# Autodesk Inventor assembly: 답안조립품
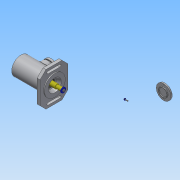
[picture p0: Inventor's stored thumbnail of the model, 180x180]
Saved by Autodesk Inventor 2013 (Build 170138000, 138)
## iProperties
Created: 2017-10
Part Number: 답안조립품
Document SubType Name: Assembly
Designer: Administrator
Author: Administrator
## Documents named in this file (20)
- C:\Users\Administrator\Desktop\471008V1005\답안조립품.iam
- C:\Users\Administrator\Desktop\471008V1005\본체.ipt
- C:\Users\Administrator\Desktop\471008V1005\V-벨트풀리.ipt
- C:\Users\Administrator\Desktop\471008V1005\너트 M10.ipt
- C:\Users\Administrator\Desktop\471008V1005\멈춤링 15 x 1.ipt
- C:\Users\Administrator\Desktop\471008V1005\멈춤링 35x1.6.ipt
- C:\Users\Administrator\Desktop\471008V1005\베어링 15 x 35 x 11.ipt
- C:\Users\Administrator\Desktop\471008V1005\볼트 M4 x 10.ipt
- C:\Users\Administrator\Desktop\471008V1005\부시1.ipt
- C:\Users\Administrator\Desktop\471008V1005\부시2.ipt
- C:\Users\Administrator\Desktop\471008V1005\사이드 커버.ipt
- 사이드 커버.ipt
- C:\Users\Administrator\Desktop\471008V1005\십자볼트 M3 x 10.ipt
- C:\Users\Administrator\Desktop\471008V1005\오일 실 15 25 7.ipt
- C:\Users\Administrator\Desktop\471008V1005\와셔 3x6.ipt
- C:\Users\Administrator\Desktop\471008V1005\와셔 4x16.ipt
- C:\Users\Administrator\Desktop\471008V1005\와셔 10x21.ipt
- C:\Users\Administrator\Desktop\471008V1005\축.ipt
- C:\Users\Administrator\Desktop\471008V1005\키 4 x 4 x 18.ipt
- C:\Users\Administrator\Desktop\471008V1005\탑 커버.ipt
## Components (2 placed, 2 different names)
1. V-벨트풀리:1
2. ISO 4017 M4 x 10:1
